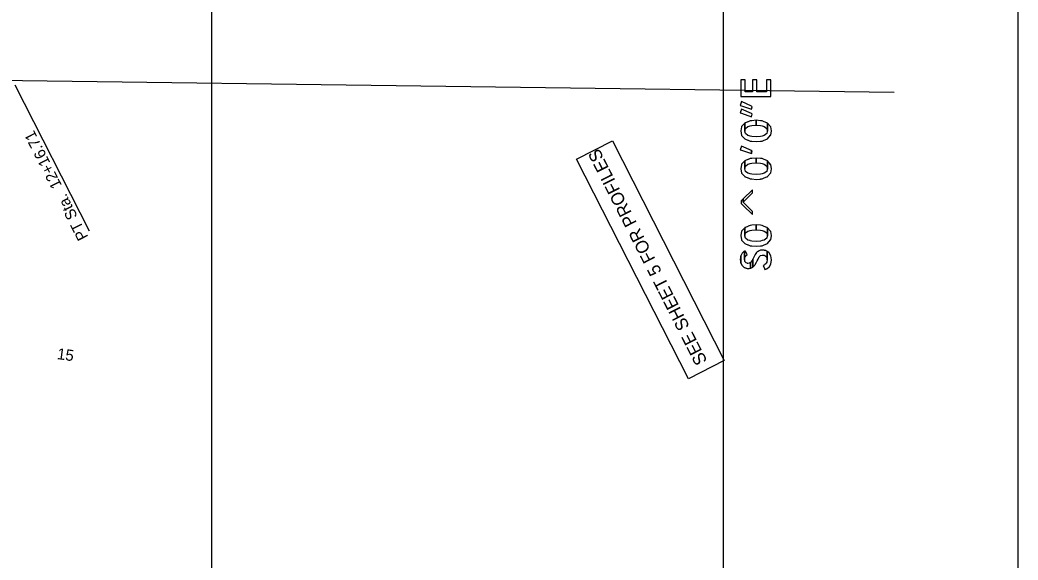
# Model space of a CAD drawing. Extents: x 557583 to 560285, y 513145 to 516544.
# Drawn here: x 559658 to 560285, y 515089 to 515428 of the extents above; entities that cross this region are included whole.
import ezdxf

# ---------------------------------------------------------------- set-up
doc = ezdxf.new("R2010")
doc.units = 0
for name, color, linetype in [('Default', 7, 'Continuous'), ('Exist Environmental Wetland Boundary Cogo Comment', 7, 'Continuous'), ('Exist Environmental Wetland Boundary Cogo Point CELL', 7, 'Continuous'), ('Prop DSN Text', 7, 'Continuous'), ('Scratch_Level_0', 7, 'Continuous'), ('Scratch_Level_4', 7, 'Continuous')]:
    doc.layers.add(name, color=color, linetype=linetype)

msp = doc.modelspace()

# ---------------------------------------------------------------- linework, layer by layer
at = {"layer": 'Default'}
for p, q in [((560099.28, 516457.65), (560099.28, 514457.65)), ((559778.26, 514977.65), (559778.26, 515457.65))]:
    msp.add_line(p, q, dxfattribs=at)
msp.add_lwpolyline([(558489.93, 514310.85), (560284.53, 514310.85), (560284.53, 516544.27), (558489.93, 516544.27)], close=True, dxfattribs=at)
at = {"layer": 'Exist Environmental Wetland Boundary Cogo Point CELL'}
msp.add_line((559701.49, 515295.84), (559654.86, 515387.43), dxfattribs=at)
at = {"layer": 'Prop DSN Text'}
msp.add_lwpolyline([(560077.52, 515203.04), (560007.27, 515341.01), (560029.84, 515352.5), (560100.09, 515214.53)], close=True, dxfattribs=at)
at = {"layer": 'Scratch_Level_0'}
for points in [[(560126.55, 515380.32), (560129.28, 515380.32), (560129.28, 515390.77), (560126.55, 515390.77), (560126.55, 515383.35), (560120.5, 515383.35), (560120.5, 515390.77), (560117.84, 515390.77), (560117.84, 515383.35), (560113.16, 515383.35), (560113.16, 515390.77), (560110.55, 515390.77), (560110.55, 515380.32), (560113.16, 515380.32), (560117.84, 515380.32), (560120.5, 515380.32)], [(560117.09, 515372.32), (560117.67, 515373.94), (560117.09, 515374.21), (560110.9, 515377.09), (560110.13, 515374.75), (560110.9, 515374.48)], [(560117.09, 515367.66), (560117.67, 515369.29), (560117.09, 515369.56), (560110.9, 515372.44), (560110.13, 515370.09), (560110.9, 515369.83)], [(560117.35, 515362.16), (560120.04, 515362.38), (560120.04, 515365.41), (560117.35, 515365.14), (560116.32, 515365.05), (560116.29, 515365.03), (560116.29, 515365.03), (560114.98, 515364.51), (560114.98, 515364.5), (560114.94, 515364.49), (560113.42, 515363.88), (560113.42, 515363.87), (560113.02, 515363.72), (560113.01, 515363.71), (560112.98, 515363.67), (560112.98, 515358.74), (560113.01, 515358.87), (560113.02, 515358.91), (560113.42, 515360.33), (560114.94, 515361.5), (560114.98, 515361.53), (560116.29, 515361.88), (560116.32, 515361.89)], [(560127.13, 515358.77), (560127.16, 515358.63), (560127.16, 515363.62), (560127.13, 515363.66), (560127.11, 515363.68), (560126.72, 515363.84), (560125.21, 515364.47), (560125.19, 515364.47), (560123.85, 515365.03), (560123.82, 515365.04), (560122.85, 515365.13), (560122.79, 515365.14), (560120.1, 515365.41), (560120.07, 515365.41), (560120.04, 515365.41), (560120.04, 515362.38), (560120.07, 515362.38), (560120.1, 515362.37), (560122.79, 515362.16), (560122.85, 515362.16), (560123.82, 515361.89), (560123.85, 515361.89), (560125.19, 515361.53), (560125.21, 515361.51), (560126.72, 515360.33), (560127.11, 515358.84)], [(560129.22, 515356.02), (560129.76, 515358.68), (560129.22, 515361.27), (560129.19, 515361.42), (560127.16, 515363.62), (560127.16, 515358.63), (560127.13, 515358.5), (560127.11, 515358.44), (560126.72, 515357.05), (560125.21, 515355.88), (560125.19, 515355.88), (560125.19, 515355.88), (560123.85, 515355.51), (560123.82, 515355.5), (560122.85, 515355.24), (560122.79, 515355.22), (560120.1, 515354.99), (560120.07, 515354.99), (560120.04, 515354.99), (560117.35, 515355.22), (560116.32, 515355.5), (560116.29, 515355.5), (560114.98, 515355.86), (560114.94, 515355.87), (560113.42, 515357.05), (560113.02, 515358.55), (560113.01, 515358.6), (560112.98, 515358.74), (560112.98, 515363.67), (560110.98, 515361.49), (560110.96, 515361.38), (560110.37, 515358.71), (560110.37, 515358.7), (560110.96, 515355.93), (560110.98, 515355.9), (560112.98, 515353.75), (560113.01, 515353.71), (560113.02, 515353.7), (560113.42, 515353.54), (560114.94, 515352.91), (560114.98, 515352.89), (560116.29, 515352.36), (560116.32, 515352.35), (560117.35, 515352.24), (560120.04, 515351.96), (560120.07, 515351.96), (560120.1, 515351.96), (560122.79, 515352.23), (560122.85, 515352.23), (560123.82, 515352.33), (560123.85, 515352.34), (560125.19, 515352.89), (560125.21, 515352.89), (560126.72, 515353.51), (560127.11, 515353.67), (560127.13, 515353.68), (560127.16, 515353.72), (560129.19, 515355.98)], [(560110.9, 515346.59), (560117.09, 515344.43), (560117.09, 515346.32), (560110.9, 515349.2), (560110.13, 515346.86)], [(560117.09, 515344.43), (560117.67, 515346.05), (560117.09, 515346.32)], [(560129.22, 515332.29), (560129.76, 515334.95), (560129.22, 515337.54), (560129.19, 515337.69), (560127.16, 515339.89), (560127.16, 515334.91), (560127.13, 515334.78), (560127.11, 515334.71), (560126.72, 515333.32), (560125.21, 515332.16), (560125.19, 515332.15), (560125.19, 515332.15), (560123.85, 515331.78), (560123.82, 515331.78), (560122.85, 515331.51), (560122.79, 515331.49), (560120.1, 515331.26), (560120.07, 515331.26), (560120.04, 515331.26), (560117.35, 515331.49), (560116.32, 515331.77), (560116.29, 515331.78), (560114.98, 515332.13), (560114.94, 515332.14), (560113.42, 515333.32), (560113.02, 515334.82), (560113.01, 515334.87), (560112.98, 515335.01), (560112.98, 515339.94), (560110.98, 515337.77), (560110.96, 515337.66), (560110.37, 515334.98), (560110.37, 515334.98), (560110.96, 515332.2), (560110.98, 515332.18), (560112.98, 515330.03), (560113.01, 515329.99), (560113.02, 515329.97), (560113.42, 515329.81), (560114.94, 515329.18), (560114.98, 515329.16), (560116.29, 515328.63), (560116.32, 515328.62), (560117.35, 515328.52), (560120.04, 515328.23), (560120.07, 515328.23), (560120.1, 515328.23), (560122.79, 515328.5), (560122.85, 515328.51), (560123.82, 515328.61), (560123.85, 515328.61), (560125.19, 515329.16), (560125.21, 515329.16), (560126.72, 515329.78), (560127.11, 515329.94), (560127.13, 515329.95), (560127.16, 515329.99), (560129.19, 515332.25)], [(560117.35, 515338.43), (560120.04, 515338.65), (560120.04, 515341.68), (560117.35, 515341.42), (560116.32, 515341.32), (560116.29, 515341.31), (560116.29, 515341.3), (560114.98, 515340.78), (560114.98, 515340.78), (560114.94, 515340.76), (560113.42, 515340.15), (560113.42, 515340.15), (560113.02, 515339.99), (560113.01, 515339.99), (560112.98, 515339.94), (560112.98, 515335.01), (560113.01, 515335.14), (560113.02, 515335.18), (560113.42, 515336.6), (560114.94, 515337.77), (560114.98, 515337.8), (560116.29, 515338.15), (560116.32, 515338.16)], [(560127.13, 515335.04), (560127.16, 515334.91), (560127.16, 515339.89), (560127.13, 515339.93), (560127.11, 515339.96), (560126.72, 515340.12), (560125.21, 515340.74), (560125.19, 515340.75), (560123.85, 515341.3), (560123.82, 515341.31), (560122.85, 515341.41), (560122.79, 515341.41), (560120.1, 515341.68), (560120.07, 515341.68), (560120.04, 515341.68), (560120.04, 515338.65), (560120.07, 515338.65), (560120.1, 515338.65), (560122.79, 515338.43), (560122.85, 515338.43), (560123.82, 515338.16), (560123.85, 515338.16), (560125.19, 515337.8), (560125.21, 515337.79), (560126.72, 515336.6), (560127.11, 515335.11)], [(560111.98, 515313.94), (560117.81, 515319.81), (560117.81, 515321.74), (560111.98, 515316.08)], [(560111.98, 515311.79), (560117.81, 515306.13), (560117.81, 515308.06), (560111.98, 515313.94), (560111.98, 515316.08), (560110.59, 515314.73), (560110.59, 515313.15)], [(560129.22, 515290.29), (560129.76, 515292.95), (560129.22, 515295.54), (560129.19, 515295.69), (560127.16, 515297.89), (560127.16, 515292.91), (560127.13, 515292.78), (560127.11, 515292.71), (560126.72, 515291.32), (560125.21, 515290.16), (560125.19, 515290.15), (560125.19, 515290.15), (560123.85, 515289.78), (560123.82, 515289.78), (560122.85, 515289.51), (560122.79, 515289.49), (560120.1, 515289.26), (560120.07, 515289.26), (560120.04, 515289.26), (560117.35, 515289.49), (560116.32, 515289.77), (560116.29, 515289.78), (560114.98, 515290.13), (560114.94, 515290.14), (560113.42, 515291.32), (560113.02, 515292.82), (560113.01, 515292.87), (560112.98, 515293.01), (560112.98, 515297.94), (560110.98, 515295.77), (560110.96, 515295.66), (560110.37, 515292.98), (560110.37, 515292.98), (560110.96, 515290.2), (560110.98, 515290.18), (560112.98, 515288.03), (560113.01, 515287.99), (560113.02, 515287.97), (560113.42, 515287.81), (560114.94, 515287.18), (560114.98, 515287.16), (560116.29, 515286.63), (560116.32, 515286.62), (560117.35, 515286.52), (560120.04, 515286.23), (560120.07, 515286.23), (560120.1, 515286.23), (560122.79, 515286.5), (560122.85, 515286.51), (560123.82, 515286.61), (560123.85, 515286.61), (560125.19, 515287.16), (560125.21, 515287.16), (560126.72, 515287.78), (560127.11, 515287.94), (560127.13, 515287.95), (560127.16, 515287.99), (560129.19, 515290.25)], [(560117.35, 515296.43), (560120.04, 515296.65), (560120.04, 515299.68), (560117.35, 515299.42), (560116.32, 515299.32), (560116.29, 515299.31), (560116.29, 515299.3), (560114.98, 515298.78), (560114.98, 515298.78), (560114.94, 515298.76), (560113.42, 515298.15), (560113.42, 515298.15), (560113.02, 515297.99), (560113.01, 515297.99), (560112.98, 515297.94), (560112.98, 515293.01), (560113.01, 515293.14), (560113.02, 515293.18), (560113.42, 515294.6), (560114.94, 515295.77), (560114.98, 515295.8), (560116.29, 515296.15), (560116.32, 515296.16)], [(560127.13, 515293.04), (560127.16, 515292.91), (560127.16, 515297.89), (560127.13, 515297.93), (560127.11, 515297.96), (560126.72, 515298.12), (560125.21, 515298.74), (560125.19, 515298.75), (560123.85, 515299.3), (560123.82, 515299.31), (560122.85, 515299.41), (560122.79, 515299.41), (560120.1, 515299.68), (560120.07, 515299.68), (560120.04, 515299.68), (560120.04, 515296.65), (560120.07, 515296.65), (560120.1, 515296.65), (560122.79, 515296.43), (560122.85, 515296.43), (560123.82, 515296.16), (560123.85, 515296.16), (560125.19, 515295.8), (560125.21, 515295.79), (560126.72, 515294.6), (560127.11, 515293.11)], [(560115.81, 515272.38), (560116.5, 515272.43), (560116.5, 515275.98), (560115.81, 515275.57), (560114.77, 515275.5), (560114.7, 515275.49), (560114.45, 515275.59), (560113.78, 515275.85), (560113.55, 515276.12), (560113.23, 515276.49), (560113.08, 515276.66), (560113.05, 515276.8), (560112.93, 515277.28), (560112.77, 515277.89), (560112.77, 515283.09), (560112.45, 515282.94), (560111.52, 515282.09), (560111.3, 515281.89), (560110.48, 515280.3), (560110.48, 515275.64), (560111.3, 515274.26), (560111.52, 515273.89), (560112.45, 515273.2), (560112.77, 515272.96), (560112.93, 515272.84), (560113.05, 515272.76), (560113.08, 515272.74), (560113.23, 515272.71), (560113.55, 515272.62), (560113.78, 515272.56), (560114.45, 515272.38), (560114.7, 515272.32), (560114.77, 515272.3)], [(560113.78, 515280.39), (560114.45, 515280.93), (560113.78, 515282.24), (560113.55, 515282.69), (560113.23, 515283.3), (560113.08, 515283.23), (560113.05, 515283.22), (560112.93, 515283.16), (560112.77, 515283.09), (560112.77, 515277.89), (560112.93, 515279.2), (560113.05, 515279.4), (560113.08, 515279.46), (560113.23, 515279.69), (560113.55, 515280.2)], [(560126.78, 515278.98), (560126.98, 515277.8), (560126.98, 515283.04), (560126.78, 515283.17), (560126.76, 515283.18), (560126.72, 515283.21), (560126.34, 515283.46), (560126.19, 515283.49), (560126.08, 515283.51), (560125.53, 515283.63), (560125.29, 515283.68), (560125.1, 515283.72), (560124.39, 515283.87), (560123.95, 515283.82), (560122.89, 515283.71), (560122.43, 515283.66), (560122.06, 515283.45), (560121.35, 515283.05), (560121.35, 515283.04), (560120.78, 515282.73), (560120.41, 515282.26), (560119.5, 515281.09), (560119.3, 515280.71), (560118.43, 515279.04), (560118.04, 515278.16), (560118.04, 515273.15), (560118.43, 515273.54), (560119.3, 515274.4), (560119.5, 515274.74), (560120.41, 515276.29), (560120.78, 515277.04), (560121.35, 515278.19), (560122.06, 515279.58), (560122.43, 515279.94), (560122.89, 515280.4), (560123.95, 515280.74), (560124.39, 515280.69), (560125.1, 515280.62), (560125.29, 515280.52), (560125.53, 515280.39), (560126.08, 515280.11), (560126.19, 515279.93), (560126.34, 515279.7), (560126.72, 515279.13), (560126.76, 515279.05)], [(560110.45, 515275.88), (560110.48, 515275.65), (560110.48, 515280.3), (560110.45, 515280.23), (560110.13, 515277.91), (560110.13, 515277.91)], [(560117.63, 515272.96), (560118.04, 515273.15), (560118.04, 515278.16), (560117.63, 515277.26), (560116.82, 515276.17), (560116.5, 515275.98), (560116.5, 515272.43), (560116.82, 515272.57)], [(560129.36, 515275.09), (560129.76, 515277.67), (560129.36, 515280.33), (560129.35, 515280.33), (560128.19, 515282.13), (560128.05, 515282.35), (560126.98, 515283.04), (560126.98, 515277.8), (560126.78, 515276.39), (560126.76, 515276.37), (560126.72, 515276.27), (560126.34, 515275.56), (560126.19, 515275.28), (560126.08, 515275.18), (560125.53, 515274.73), (560125.29, 515274.53), (560125.1, 515274.46), (560124.41, 515274.19), (560125.1, 515272.68), (560125.29, 515272.27), (560125.53, 515271.76), (560126.08, 515271.94), (560126.19, 515271.98), (560126.34, 515272.03), (560126.72, 515272.15), (560126.76, 515272.18), (560126.78, 515272.19), (560126.98, 515272.33), (560128.05, 515273.1), (560128.19, 515273.2), (560129.35, 515275.06)]]:
    msp.add_lwpolyline(points, close=True, dxfattribs=at)
at = {"layer": 'Scratch_Level_4'}
msp.add_line((559402.36, 515393.66), (560206.69, 515383.08), dxfattribs=at)

# ---------------------------------------------------------------- texts
at = {"layer": 'Exist Environmental Wetland Boundary Cogo Comment'}
msp.add_text('15', height=7, rotation=352.09376, dxfattribs=at).set_placement((559680.86, 515215.45))
at = {"layer": 'Exist Environmental Wetland Boundary Cogo Point CELL'}
msp.add_text('PT Sta.  12+16.71', height=7, rotation=116.98193, dxfattribs=at).set_placement((559700.85, 515292.06))
at = {"layer": 'Prop DSN Text'}
msp.add_text('SEE SHEET 5 FOR PROFILES', height=8, rotation=116.98193, dxfattribs=at).set_placement((560089.6, 515214.09))

doc.saveas('drawing.dxf')
